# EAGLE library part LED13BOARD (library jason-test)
Rotary encoder LED board (13 LEDs)
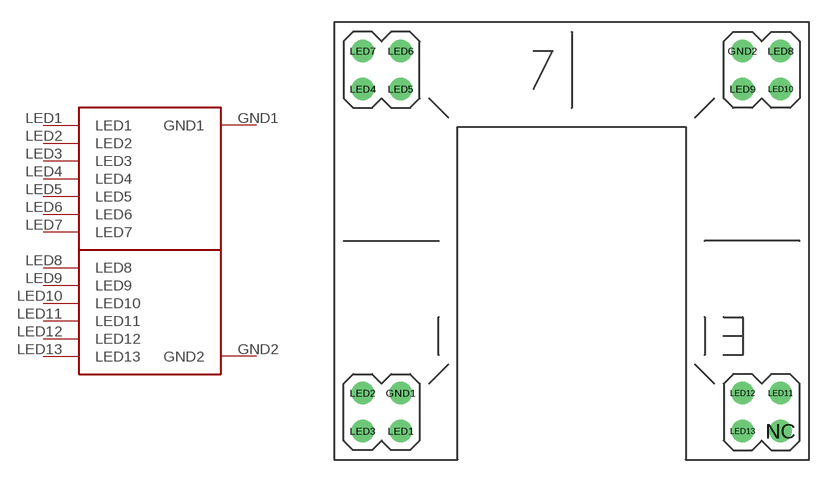
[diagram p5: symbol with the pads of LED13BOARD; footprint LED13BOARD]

Designator prefix -

## LED13BOARD  [LED13BOARD]
GND1  GND1
GND2  GND2
LED1  LED1
LED2  LED2
LED3  LED3
LED4  LED4
LED5  LED5
LED6  LED6
LED7  LED7
LED8  LED8
LED9  LED9
LED10  LED10
LED11  LED11
LED12  LED12
LED13  LED13

## Footprint LED13BOARD (pad centres in mm)
Rotary encoder LED board
drill 1 round: GND1 3.81,3.81; GND2 26.67,26.67; LED1 3.81,1.27; LED2 1.27,3.81; LED3 1.27,1.27; LED4 1.27,24.13; LED5 3.81,24.13; LED6 3.81,26.67; LED7 1.27,26.67; LED8 29.21,26.67; LED9 26.67,24.13; LED10 29.21,24.13; LED11 29.21,3.81; LED12 26.67,3.81; LED13 26.67,1.27; NC 29.21,1.27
